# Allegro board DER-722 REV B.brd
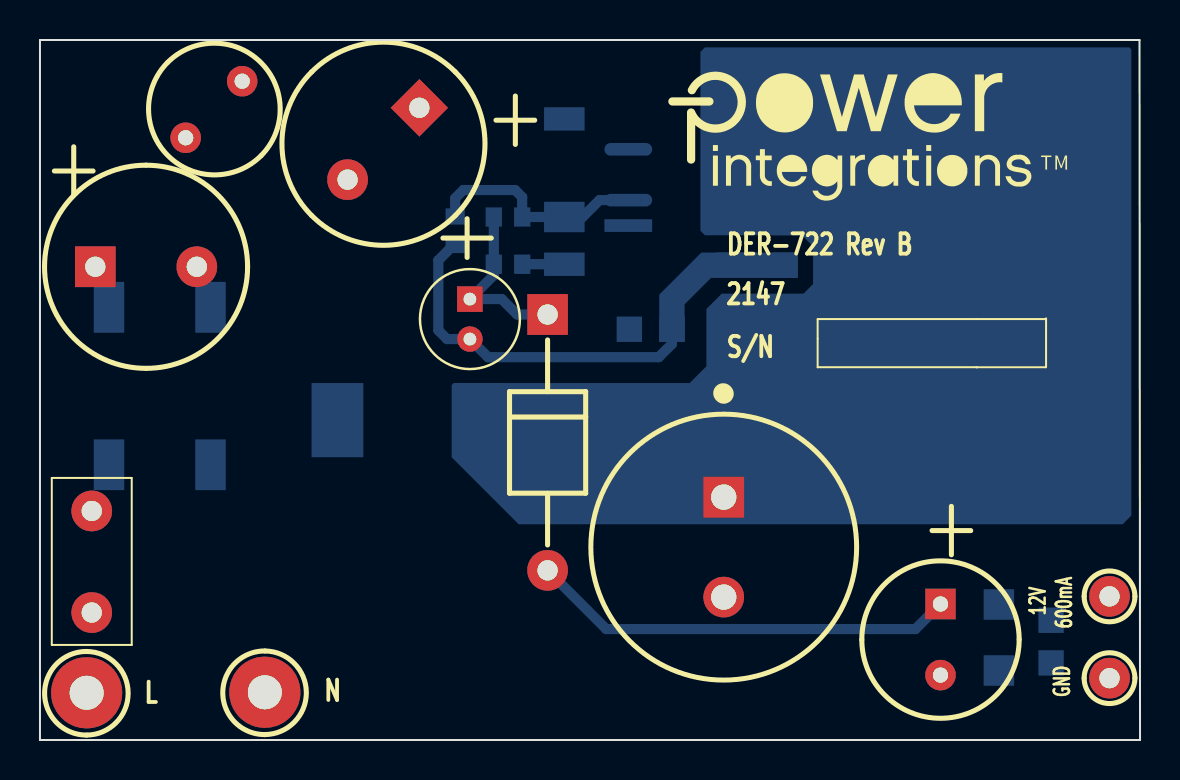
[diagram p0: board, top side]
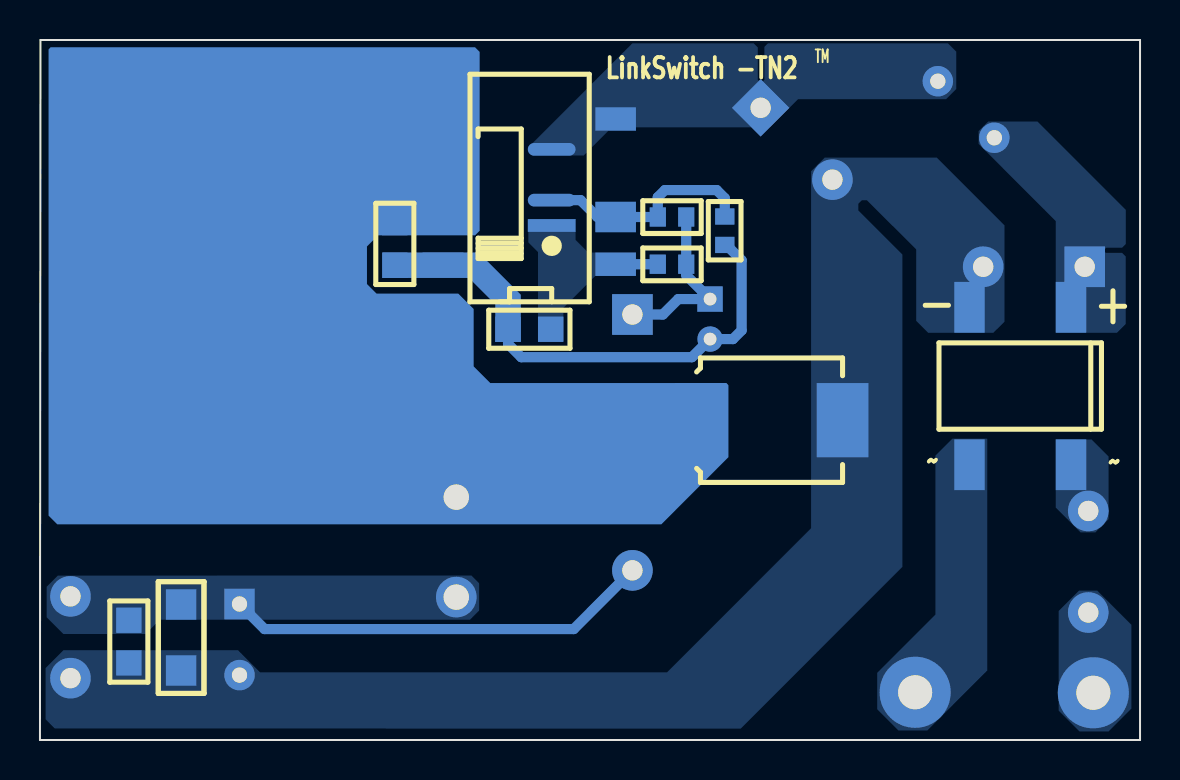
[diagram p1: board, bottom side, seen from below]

Outline 55.04 x 35.01 mm; copper layers: TOP, BOTTOM. Coordinates in mm from the lower left corner of the outline.
Outline path: 0,35.01 0,0 55.04,0 55.02,35.01 0,35.01

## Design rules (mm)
constraint set DEFAULT: min track width 0.508

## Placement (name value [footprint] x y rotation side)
C1  15 uF  [PIPOLCAPCYLD400LS200040]  2.77 23.67 0 top
C2  15 uF  [PIPOLCAPCYLD400LS200040]  18.98 31.62 225 top
C3  100 nF  [PISMC0805]  29.49 20.54 0 bottom
C4  10 uF  [PIPOLCAPCLYD5MMLS2MM025]  21.51 21.05 270 top
C5  220 uF  [PIPOLCAPCLYD320LS140030]  45.06 6.8 270 top
C6  100 nF  [PISMC1206]  47.98 6.78 270 bottom
D1  DF06S-E3/45  [PISMDDFS]  3.45 21.59 180 bottom
D2  STTH3R06S  [PISMDO214AB12]  22 16 180 bottom
D3  BYV26C  [PIDV200X150X040SOD57]  25.4 21.28 270 top
F1  1 A  [PI_RST_MICROFUSE]  2.59 11.46 270 top
L1  470 uH  [PICHOKETOKINVD276H413LS158D030]  7.29 30.12 45 top
L2  390 uH  [PICHOKEVD13XXLS5MMD050]  34.21 9.65 270 top
NOREF  -  []  -228.6 -137.16 0 top
NOREF#2  -  []  -150.56 88.4 0 top
NOREF#3  -  []  55.02 35.01 270 top
NOREF#4  -  []  0 35.01 0 top
NOREF#5  -  []  107.65 55.9 0 top
R1  2.49 k  [PISMR0603]  20.78 26.18 270 bottom
R2  12.1 k  [PISMR0603]  24.13 26.16 180 bottom
R3  27 k  [PISMR0603]  24.13 23.79 180 bottom
R4  20 k  [PISMR0805]  50.6 5.99 270 bottom
R5  0.0  [PISMR0805]  37.29 23.74 90 bottom
TP1  WHT  [PITPKEYSTONE125X125]  2.34 2.36 0 top
TP2  BLK  [PITPKEYSTONE125X125]  11.25 2.39 0 top
TP3  RED  [PITPKEYSTONE100X100]  53.52 7.18 270 top
TP4  BLK  [PITPKEYSTONE100X100]  53.52 3.09 270 top
U1  LNK3208D  [PISMSO8DNSHORT5678]  29.44 25.73 90 bottom
U2  LNK3208G  [PIICSMD8CSHORT567IPC]  26.24 23.79 90 bottom

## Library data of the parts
C1 C2 = CAP POL: alternate symbols: (pipolcapclyd400x630ls200030h)
C3 C6 = CAP NP
C4 = CAP POL: alternate symbols: (pipolcapclyd5mm030,pipolcapclyd5x5mm030H)
C5 = CAP POL: alternate symbols: (pipolcapclyd320ls140030430h)
D1 = DIODE BRIDGE_+-~~
D2 = DIODE
D3 = DIODE: alternate symbols: (pidax425x150040sod57,pidv200x150x040sod57r)
F1 = FUSE: alternate symbols: (pirstmicrofusehoz)
L1 L2 = INDUCTOR
R1-R4 = R
R5 = R: alternate symbols: (pismr0805_1)
TP1-TP3 = TESTPOINT
TP4 = TESTPOINT: alternate symbols: (TP_TH_CR2_D1_1)
U1 = LNK32XX_8C
U2 = LNK32XX_8G

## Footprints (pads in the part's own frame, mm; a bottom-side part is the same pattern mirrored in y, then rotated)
PI_RST_MICROFUSE
  round 2.032 hole 1.016: 1(0,0) 2(5.08,0)
PICHOKETOKINVD276H413LS158D030
  round 1.524 hole 0.762: 1(0,0) 2(4,0)
PICHOKEVD13XXLS5MMD050
  rect 2.032x2.032 hole 1.27: 1(-2.5,0)
  round 2.032 hole 1.27: 2(2.5,0)
PIDV200X150X040SOD57
  rect 2.032x2.032 hole 1.016: 1(0,0)
  round 2.032 hole 1.016: 2(12.795,0)
PIICSMD8CSHORT567IPC
  rect 1.168x2.032 smd: 1(0,0) 4(7.264,0) 5(7.264,8.636) 8(0,8.636)
  rect 1.524x2.032 smd: 2(2.362,0) 6(4.902,8.636) 7(2.362,8.636)
PIPOLCAPCLYD5MMLS2MM025
  rect 1.27x1.27 hole 0.635: 1(-1,0)
  round 1.27 hole 0.635: 2(1,0)
PIPOLCAPCLYD320LS140030
  rect 1.524x1.524 hole 0.762: 1(0,0)
  round 1.524 hole 0.762: 2(3.556,0)
PIPOLCAPCYLD400LS200040
  rect 2.032x2.032 hole 1.016: 1(0,0)
  round 2.032 hole 1.016: 2(5.08,0)
PISMC0805
  rect 1.27x1.27 smd: 1(0,0) 2(2.134,0)
PISMC1206
  rect 1.524x1.524 smd: 1(0,0) 2(3.302,0)
PISMDDFS
  rect 1.524x2.54 smd: 1(0,0.051) 2(-5.08,0.051) 3(0,-7.823) 4(-5.08,-7.823)
PISMDO214AB12
  rect 2.591x3.708 smd: 1(0,0) 2(7.112,0)
PISMR0603
  rect 0.813x0.965 smd: 1(0,0) 2(1.422,0)
PISMR0805
  rect 1.27x1.27 smd: 1(0,0) 2(2.134,0)
PISMSO8DNSHORT5678
  rect 0.635x2.388 smd: 1(0,0)
  oval 0.635x2.388 smd: 2(1.27,0) 4(3.81,0) 5(3.81,4.978) 6(2.54,4.978) 7(1.27,4.978) 8(0,4.978)
PITPKEYSTONE100X100
  round 2.032 hole 1.016: 1(0,0)
PITPKEYSTONE125X125
  round 3.556 hole 1.702: 1(0,0)

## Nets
SOURCE: U1.6 U1.7 U1.8
N4183667: C2.1 L1.2 U1.4 U2.4
N4183681: C1.2 C2.2 C5.2 C6.2 D1.2 D2.2 R4.2 TP4.1
N4183882: C3.2 C4.2 D2.1 L2.1 R1.2 R5.2 U1.5(S) U2.5 U2.6 U2.7
N4183892: C3.1 R3.1 U1.1 U2.1
N4184371: R1.1 R2.1 U1.2 U2.2
N4185002: C5.1 C6.1 D3.2 L2.2 R4.1 TP3.1
N4185015: C4.1 D3.1 R2.2 R3.2
N4189997: F1.2 TP1.1
N4191135: D1.3 F1.1
N4191219: C1.1 D1.1 L1.1
N4191491: D1.4 TP2.1
N4224221: R5.1 U2.8

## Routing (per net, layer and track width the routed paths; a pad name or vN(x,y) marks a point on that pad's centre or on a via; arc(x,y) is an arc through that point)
N4183882: length 17.9
  BOTTOM w0.508: R1.2 20.7,24.76 19.94,23.99 19.94,20.49 20.37,20.05 C4.2 22.42,19.15 30.96,19.15 31.62,19.81 C3.2
N4183892: length 2.1
  BOTTOM w0.508: 26.26,23.8 26.26,23.79 U2.1 R3.1
N4184371: length 11.2
  BOTTOM w0.508: R1.1 20.78,27.1 21.18,27.5 23.77,27.5 24.13,27.15 R2.1 U2.2 26.26,26.16 26.26,26.16 27.16,26.16 28,27 U1.2
N4185002: length 21.4
  BOTTOM w0.508: C5.1 43.81,5.55 28.34,5.55 D3.2
N4185015: length 8.8
  BOTTOM w0.508: R2.2 R3.2 22.71,23.25 C4.1 23.1,22.05 23.88,21.28 D3.1

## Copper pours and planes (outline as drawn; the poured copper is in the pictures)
N4183667 on BOTTOM: 26.43,30.64 27.84,29.23 30.35,29.23 30.45,29.33 30.45,29.79 25.4,34.84 19.33,34.84 19.13,34.64 19.13,33.01 19.02,32.91 18.9,32.91 18.8,33.01 18.8,34.67 18.62,34.84 9.61,34.84 9.19,34.43 9.19,32.56 9.7,32.05 17.11,32.05 18.52,30.64
N4183681 on BOTTOM: 23.67,3.38 16.46,10.59 16.46,28.44 15.77,29.13 10.17,29.13 6.78,25.74 6.78,20.92 7.15,20.55 7.16,20.55 7.34,20.37 10.6,20.37 11.2,20.97 11.2,24.54 12.37,25.71 12.38,25.71 13.67,26.99 13.92,26.99 14.1,26.82 14.1,26.49 11.89,24.28 11.89,8.66 14.91,5.64 19.98,0.57 37.74,0.57 37.75,0.58 54.31,0.58 54.76,1.04 54.76,3.6 53.87,4.49 45.14,4.49 44.03,3.38
N4183882 on BOTTOM (solid shape): 54.61,34.54 54.61,11.22 54.18,10.79 23.95,10.79 20.6,14.14 20.6,17.75 20.7,17.85 32.51,17.85 33.35,18.69 33.35,21.56 34.11,22.32 38.2,22.32 38.68,22.8 38.68,24.68 38.13,25.24 33.27,25.24 33.05,25.47 33.05,34.41 33.27,34.64 54.51,34.64
N4183892 on BOTTOM: 25.25,24.38 25.25,23.21 27.25,23.21 28.85,21.61 28.85,19.91 30.12,19.91 30.12,24.4 30.61,24.89 30.61,26.03 30.58,26.06 28.24,26.06 28.24,25.01 27.61,24.38
N4185002 on BOTTOM: 49.76,5.3 53.87,5.3 54.71,6.14 54.71,7.66 54.15,8.22 46.21,8.22 46.2,8.22 33.45,8.22 33.07,7.84 33.07,6.47 33.53,6.01 49.05,6.01
N4189997 on BOTTOM: 3.05,7.47 4.07,6.45 4.07,1.47 3.03,0.43 1.57,0.43 0.43,1.57 0.43,5.76 2.14,7.47
N4191135 on BOTTOM: 2.42,15.03 1.57,14.18 1.57,11.04 2.24,10.38 2.97,10.38 4.22,11.63 4.22,15.03
N4191219 on BOTTOM: 0.72,20.8 0.72,24.18 0.9,24.36 1.71,24.36 1.8,24.45 1.8,24.51 1.69,24.62 0.9,24.62 0.72,24.8 0.71,24.8 0.71,26.51 5.13,30.93 7.59,30.93 8.08,30.45 8.08,29.81 4.22,25.95 4.22,20.37 1.15,20.37
N4191491 on BOTTOM: 9.55,14.91 9.39,15.07 7.66,15.07 7.65,15.06 7.65,3.47 10.64,0.48 12.09,0.48 13.15,1.54 13.15,3.36 10.24,6.27 10.24,14.22
N4224221 on BOTTOM (solid shape): 37.9,23.11 33.58,23.11 32.26,21.79 32.26,19.91 30.99,19.91 30.99,22.27 33.1,24.38 37.9,24.38

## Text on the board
Ref Des/Silkscreen Bottom: TM | LinkSwitch -TN2
Ref Des/Silkscreen Top: 12V | GND | 600mA | L | N | 2147 | DER-722 Rev B | S/N
User.6: 14.  FAB HOUSE LOGO,DATE CODE TO BE IN SILK SCREEN ONLY.DO NOT USE COPPER. | 13.  MATERIAL FR4 COPPER 2oz THICKNESS 0.062"
User.8: FIGURE | FINISHED_SIZE | 25.0 | 30.0 | 40.0 | 50.0 | 67.0 | DRILL CHART: TOP to BOTTOM | ALL UNITS ARE IN MILS | TOLERANCE_DRILL | +3.0/-3.0 | +0.0/-0.0 | PLATED | QTY | 2 | 4 | 10
